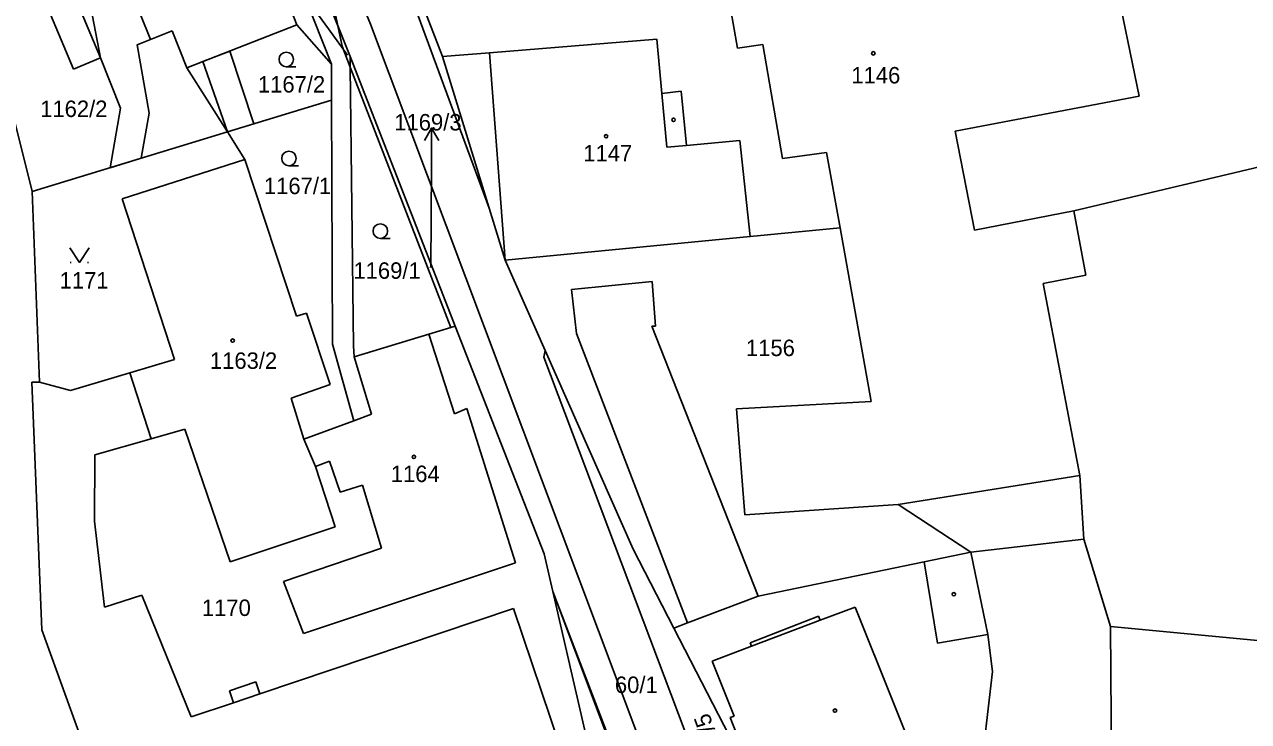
# Model space of a CAD drawing. Extents: x -670359 to -668019, y -978807 to -976674.
# Drawn here: x -670231.4 to -670104.9, y -977942.9 to -977870.8 of the extents above; entities that cross this region are included whole.
import ezdxf

# ---------------------------------------------------------------- set-up
doc = ezdxf.new("R2010")
doc.units = 0
for name, color, linetype in [('Hranice parcel', 7, 'Continuous'), ('Parcelní čísla', 7, 'Continuous'), ('Vnitřní kresba', 7, 'Continuous'), ('Věcná břemena k části', 7, 'Continuous'), ('Značky budov', 7, 'Continuous'), ('Značky kultur', 7, 'Continuous')]:
    doc.layers.add(name, color=color, linetype=linetype)

msp = doc.modelspace()

# ---------------------------------------------------------------- linework, layer by layer
at = {"layer": 'Hranice parcel'}
for points in [[(-670183.39, -977889.81), (-670193.56, -977862.25), (-670201.26, -977845.22), (-670205.62, -977834.5), (-670231.98, -977771.32), (-670242.71, -977745.05), (-670249.53, -977728.04), (-670253.85, -977714.41), (-670254.54, -977710.9), (-670255.07, -977705.75), (-670255.17, -977699.87), (-670254.7, -977694.67), (-670252.82, -977684.15), (-670242.83, -977643.13)], [(-670199.01, -977870.96), (-670199.39, -977869.14), (-670211.12, -977840.59)], [(-670211.12, -977840.59), (-670199.01, -977870.96)], [(-670208.71, -977852.13), (-670199.68, -977874.91)], [(-670223.55, -977874.27), (-670229.81, -977859.3)], [(-670232.52, -977860.64), (-670226.34, -977875.43)], [(-670203.25, -977870.84), (-670205.66, -977864.66)], [(-670191.21, -977866.33), (-670188.19, -977874.13)], [(-670118.79, -977865.64), (-670116.23, -977878.21)], [(-670219.45, -977869.7), (-670218.37, -977872.37)], [(-670230.6, -977888.08), (-670234.84, -977871.23)], [(-670218.37, -977872.37), (-670216.15, -977871.47)], [(-670216.15, -977871.47), (-670214.61, -977875.29)], [(-670214.61, -977875.29), (-670203.25, -977870.84)], [(-670203.25, -977870.84), (-670199.68, -977874.91)], [(-670197.74, -977875.22), (-670198.57, -977873.06), (-670199.01, -977870.96)], [(-670199.01, -977870.96), (-670197.75, -977874.12)], [(-670166.05, -977872.34), (-670183.34, -977873.74)], [(-670165.53, -977877.95), (-670166.05, -977872.34)], [(-670226.34, -977875.43), (-670223.55, -977874.27)], [(-670197.75, -977874.12), (-670186.89, -977901.98)], [(-670197.75, -977874.12), (-670197.74, -977875.22)], [(-670183.34, -977873.74), (-670188.19, -977874.13)], [(-670188.19, -977874.13), (-670183.39, -977889.81)], [(-670214.61, -977875.29), (-670210.42, -977881.92)], [(-670199.68, -977874.91), (-670199.66, -977878.63)], [(-670187.35, -977902.12), (-670197.74, -977875.22)], [(-670197.74, -977875.22), (-670197.4, -977904.04)], [(-670163.53, -977877.72), (-670165.53, -977877.95)], [(-670163.01, -977883.32), (-670163.53, -977877.72)], [(-670210.42, -977881.92), (-670199.66, -977878.63)], [(-670199.56, -977903.86), (-670199.66, -977878.63)], [(-670116.23, -977878.21), (-670135.23, -977881.84)], [(-670230.6, -977888.08), (-670210.42, -977881.92)], [(-670210.42, -977881.92), (-670208.63, -977884.76)], [(-670135.23, -977881.84), (-670133.22, -977892.09)], [(-670157.48, -977882.8), (-670163.01, -977883.32)], [(-670156.43, -977892.73), (-670157.48, -977882.8)], [(-670221.3, -977888.83), (-670208.63, -977884.76)], [(-670203.3, -977900.96), (-670208.63, -977884.76)], [(-670229.85, -977907.79), (-670230.6, -977888.08)], [(-670221.3, -977888.83), (-670215.9, -977905.43)], [(-670183.39, -977889.81), (-670181.74, -977895.19)], [(-670133.22, -977892.09), (-670122.96, -977890.08)], [(-670122.96, -977890.08), (-670121.73, -977896.73)], [(-670147.13, -977891.82), (-670156.43, -977892.73)], [(-670143.91, -977909.77), (-670147.13, -977891.82)], [(-670156.43, -977892.73), (-670181.74, -977895.19)], [(-670181.74, -977895.19), (-670177.61, -977904.51)], [(-670121.73, -977896.73), (-670126.14, -977897.58)], [(-670126.14, -977897.58), (-670122.36, -977917.44)], [(-670202.26, -977900.64), (-670203.3, -977900.96)], [(-670199.83, -977908.02), (-670202.26, -977900.64)], [(-670187.35, -977902.12), (-670189.63, -977902.81)], [(-670186.89, -977901.98), (-670187.35, -977902.12)], [(-670186.89, -977901.98), (-670177.71, -977925.53)], [(-670189.63, -977902.81), (-670197.33, -977905.16)], [(-670186.97, -977911.07), (-670189.63, -977902.81)], [(-670199.56, -977903.86), (-670197.38, -977911.79)], [(-670197.4, -977904.04), (-670197.33, -977905.16)], [(-670156.36, -977961.27), (-670157.99, -977957.53), (-670177.75, -977905.2), (-670177.61, -977904.51)], [(-670177.61, -977904.51), (-670168.51, -977925.03)], [(-670220.51, -977906.81), (-670215.9, -977905.43)], [(-670197.33, -977905.16), (-670195.53, -977911.09)], [(-670226.65, -977908.63), (-670220.51, -977906.81)], [(-670220.51, -977906.81), (-670218.32, -977913.63)], [(-670230.65, -977907.8), (-670229.85, -977907.79)], [(-670229.61, -977933.38), (-670230.65, -977907.8)], [(-670229.85, -977907.79), (-670226.65, -977908.63)], [(-670203.84, -977909.43), (-670199.83, -977908.02)], [(-670202.52, -977913.68), (-670203.84, -977909.43)], [(-670157.84, -977910.55), (-670143.91, -977909.77)], [(-670185.69, -977910.52), (-670186.97, -977911.07)], [(-670180.68, -977926.47), (-670185.69, -977910.52)], [(-670156.96, -977921.51), (-670157.84, -977910.55)], [(-670197.38, -977911.79), (-670202.52, -977913.68)], [(-670195.53, -977911.09), (-670197.38, -977911.79)], [(-670214.83, -977912.63), (-670218.32, -977913.63)], [(-670210.13, -977926.34), (-670214.83, -977912.63)], [(-670218.32, -977913.63), (-670224.13, -977915.29)], [(-670202.52, -977913.68), (-670201.33, -977916.49)], [(-670224.13, -977915.29), (-670224.18, -977922.16)], [(-670201.33, -977916.49), (-670199.89, -977915.94)], [(-670199.89, -977915.94), (-670198.79, -977919.14)], [(-670201.33, -977916.49), (-670199.3, -977922.74)], [(-670198.79, -977919.14), (-670196.47, -977918.44)], [(-670196.47, -977918.44), (-670194.51, -977924.93)], [(-670122.36, -977917.44), (-670121.93, -977924)], [(-670141.11, -977920.42), (-670156.96, -977921.51)], [(-670133.62, -977925.36), (-670141.11, -977920.42)], [(-670224.18, -977922.16), (-670223.13, -977931.05)], [(-670199.3, -977922.74), (-670210.13, -977926.34)], [(-670194.51, -977924.93), (-670204.62, -977928.38)], [(-670133.62, -977925.36), (-670121.93, -977924)], [(-670121.93, -977924), (-670119.19, -977933.05)], [(-670177.71, -977925.53), (-670176.81, -977929.42)], [(-670168.51, -977925.03), (-670164.29, -977933.2)], [(-670138.43, -977926.36), (-670133.62, -977925.36)], [(-670131.84, -977933.85), (-670133.62, -977925.36)], [(-670202.58, -977933.75), (-670180.68, -977926.47)], [(-670155.58, -977929.92), (-670138.43, -977926.36)], [(-670204.62, -977928.38), (-670202.58, -977933.75)], [(-670223.13, -977931.05), (-670219.28, -977929.8)], [(-670219.28, -977929.8), (-670214.16, -977942.39)], [(-670172.63, -978082.94), (-670171.28, -978083.15), (-670170.18, -978076.11), (-670165.52, -978053.97), (-670162.38, -978042.27), (-670156.72, -978020.75), (-670154.86, -978010.1), (-670154.63, -978006.17), (-670154.76, -977993.05), (-670158.01, -977978.52), (-670176.81, -977929.42)], [(-670176.81, -977929.42), (-670173.29, -977944.67)], [(-670162.88, -977932.67), (-670155.58, -977929.92)], [(-670207.08, -977940.01), (-670180.87, -977931.18)], [(-670180.87, -977931.18), (-670176.09, -977945.37)], [(-670224.12, -977948.54), (-670229.61, -977933.38)], [(-670164.29, -977933.2), (-670162.88, -977932.67)], [(-670164.29, -977933.2), (-670155.09, -977951.04)], [(-670119.19, -977933.05), (-670088.41, -977935.95)], [(-670119.06, -977951.97), (-670119.19, -977933.05)], [(-670131.39, -977937.69), (-670131.84, -977933.85)], [(-670210.21, -977939.69), (-670207.49, -977938.77)], [(-670207.49, -977938.77), (-670207.08, -977940.01)], [(-670133.18, -977953.11), (-670131.39, -977937.69)], [(-670209.8, -977940.92), (-670210.21, -977939.69)], [(-670214.16, -977942.39), (-670209.8, -977940.92)]]:
    msp.add_lwpolyline(points, dxfattribs=at)
at = {"layer": 'Parcelní čísla'}
for p, q in [((-670198.03, -977873.97), (-670199.99, -977871.26)), ((-670190.08, -977882.82), (-670189.33, -977881.52)), ((-670189.42, -977895.94), (-670189.35, -977885.52))]:
    msp.add_line(p, q, dxfattribs=at)
for points in [[(-670199.99, -977871.26), (-670202.34, -977868.02), (-670200.97, -977868.64)], [(-670189.35, -977885.52), (-670189.33, -977881.52), (-670188.58, -977882.82)]]:
    msp.add_lwpolyline(points, dxfattribs=at)
at = {"layer": 'Vnitřní kresba'}
for points in [[(-670159.81, -977861.27), (-670157.73, -977873.28)], [(-670157.73, -977873.28), (-670155.09, -977872.9)], [(-670155.09, -977872.9), (-670153.09, -977884.67)], [(-670183.34, -977873.74), (-670181.74, -977895.19)], [(-670165.53, -977877.95), (-670165.01, -977883.51)], [(-670122.96, -977890.08), (-670084.47, -977880.95)], [(-670165.01, -977883.51), (-670163.01, -977883.32)], [(-670153.09, -977884.67), (-670148.53, -977884.06)], [(-670148.53, -977884.06), (-670147.13, -977891.82)], [(-670174.88, -977898.2), (-670166.55, -977897.37)], [(-670174.35, -977902.76), (-670174.88, -977898.2)], [(-670166.55, -977897.37), (-670166.18, -977902.01)], [(-670166.18, -977902.01), (-670166.58, -977902.01)], [(-670166.58, -977902.01), (-670155.58, -977929.92)], [(-670162.88, -977932.67), (-670174.35, -977902.76)], [(-670141.11, -977920.42), (-670122.36, -977917.44)], [(-670138.43, -977926.36), (-670137.05, -977934.77)], [(-670149.19, -977932.39), (-670145.58, -977931.03)], [(-670145.58, -977931.03), (-670137.56, -977951)], [(-670156.41, -977934.71), (-670149.35, -977931.96)], [(-670156.27, -977935.07), (-670149.19, -977932.39)], [(-670149.35, -977931.96), (-670149.19, -977932.39)], [(-670156.27, -977935.07), (-670156.41, -977934.71)], [(-670137.05, -977934.77), (-670131.84, -977933.85)], [(-670160.35, -977936.61), (-670156.27, -977935.07)], [(-670158.07, -977942.3), (-670160.35, -977936.61)], [(-670209.8, -977940.92), (-670207.08, -977940.01)], [(-670158.47, -977942.46), (-670158.07, -977942.3)], [(-670155.09, -977951.04), (-670158.47, -977942.46)]]:
    msp.add_lwpolyline(points, dxfattribs=at)
at = {"layer": 'Věcná břemena k části'}
for points in [[(-670231.37, -977794.32), (-670226.31, -977792.17), (-670203.33, -977848.99), (-670196.72, -977863.94), (-670192.84, -977861.8), (-670191.21, -977866.33), (-670191.12, -977866.56), (-670196.22, -977869.36), (-670195.63, -977870.79), (-670152.49, -977985.64), (-670151.43, -977993.09), (-670152.31, -978015.47), (-670159.21, -978043.03)], [(-670159.21, -978043.03), (-670166.44, -978073.84), (-670169.93, -978096.39), (-670171.6, -978117.05), (-670173.62, -978117.69), (-670174.87, -978118.08), (-670174.67, -978116.45), (-670172.91, -978096.03), (-670169.38, -978073.26), (-670162.13, -978042.33), (-670155.29, -978015.05), (-670154.43, -977993.25), (-670155.41, -977986.38), (-670176.81, -977929.42), (-670177.71, -977925.53), (-670186.89, -977901.98), (-670197.75, -977874.12), (-670224.71, -977806.51), (-670226.38, -977803.45)], [(-670226.69, -977857.91), (-670223.83, -977856.99), (-670221.99, -977863.19), (-670220.99, -977865.75), (-670221.4, -977867.26), (-670220.69, -977869.01), (-670219.45, -977869.7), (-670218.37, -977872.37), (-670219.76, -977872.93), (-670218.52, -977879.98), (-670219.34, -977884.64), (-670222.56, -977885.63), (-670221.48, -977879.46), (-670223.55, -977874.27), (-670226.69, -977857.91)], [(-670212.98, -977874.65), (-670210.19, -977873.56), (-670207.69, -977881.09), (-670210.42, -977881.92), (-670212.98, -977874.65)]]:
    msp.add_lwpolyline(points, dxfattribs=at)
at = {"layer": 'Značky budov'}
for centre in [(-670143.69, -977873.8), (-670171.3, -977882.37), (-670209.89, -977903.49), (-670191.16, -977915.51), (-670147.65, -977941.73)]:
    msp.add_circle(centre, 0.175, dxfattribs=at)
at = {"layer": 'Značky kultur'}
for p, q in [((-670204.35, -977875.18), (-670203.35, -977875.18)), ((-670204.07, -977885.41), (-670203.07, -977885.41)), ((-670194.63, -977892.92), (-670193.63, -977892.92)), ((-670226.68, -977895.41), (-670226.58, -977895.41)), ((-670224.88, -977895.41), (-670224.78, -977895.41))]:
    msp.add_line(p, q, dxfattribs=at)
msp.add_lwpolyline([(-670226.73, -977893.91), (-670225.73, -977895.41), (-670224.73, -977893.91)], dxfattribs=at)
for centre, radius in [((-670204.35, -977874.43), 0.75), ((-670143.69, -977873.8), 0.175), ((-670164.33, -977880.67), 0.175), ((-670171.3, -977882.37), 0.175), ((-670204.07, -977884.66), 0.75), ((-670194.63, -977892.17), 0.75), ((-670209.89, -977903.49), 0.175), ((-670191.16, -977915.51), 0.175), ((-670135.37, -977929.71), 0.175), ((-670147.65, -977941.73), 0.175)]:
    msp.add_circle(centre, radius, dxfattribs=at)

# ---------------------------------------------------------------- texts
at = {"layer": 'Parcelní čísla'}
for s, height, p in [('1168/3', 0.1, (-670198.26, -977873.97)), ('1146', 1.7, (-670145.96, -977876.91)), ('1167/2', 1.7, (-670207.28, -977877.85)), ('1162/2', 1.7, (-670229.78, -977880.38)), ('1169/3', 1.7, (-670193.19, -977881.77)), ('1147', 1.7, (-670173.66, -977884.97)), ('1167/1', 1.7, (-670206.66, -977888.35)), ('1169/1', 1.7, (-670197.41, -977897.1)), ('1169/3', 0.1, (-670189.65, -977895.94)), ('1171', 1.7, (-670227.77, -977898.11)), ('1156', 1.7, (-670156.85, -977905.09)), ('1163/2', 1.7, (-670212.24, -977906.41)), ('1164', 1.7, (-670193.55, -977918.11)), ('1170', 1.7, (-670213.07, -977931.95)), ('60/1', 1.7, (-670170.39, -977939.91))]:
    msp.add_text(s, height=height, dxfattribs=at).set_placement(p)
msp.add_text('60/5', height=1.7, rotation=110.1673, dxfattribs=at).set_placement((-670159.17, -977946.03))

doc.saveas('drawing.dxf')
